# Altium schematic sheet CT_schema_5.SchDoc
size 203 x 169 mm
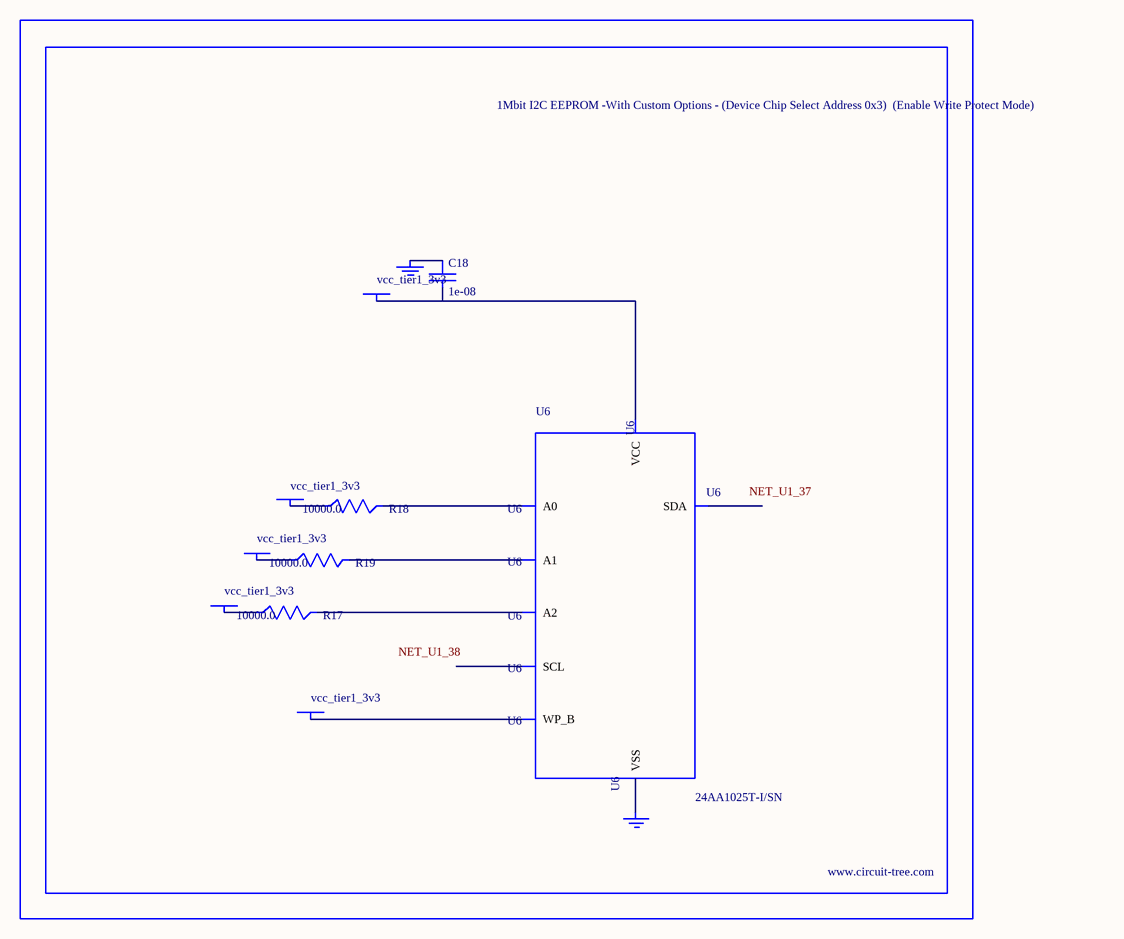
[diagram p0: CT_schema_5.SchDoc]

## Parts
BORDER4  (no value)
C18  1e-08  [C0402]
GND_INSTANCE_4_0  (no value)
GND_INSTANCE_4_1  (no value)
POWER_INSTANCE_4_0  vcc_tier1_3v3
POWER_INSTANCE_4_1  vcc_tier1_3v3
POWER_INSTANCE_4_2  vcc_tier1_3v3
POWER_INSTANCE_4_3  vcc_tier1_3v3
POWER_INSTANCE_4_4  vcc_tier1_3v3
R17  10000.0  [R0603]
R18  10000.0  [R0603]
R19  10000.0  [R0603]
U6  24AA1025T-I/SN  [SOIC-8]

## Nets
NetC18_1: C18.1 GND_INSTANCE_4_0.0(GND)
NetC18_2: C18.2 POWER_INSTANCE_4_4.0(PWR) U6.8(VCC)
NetGND_INSTANCE_4_1_0: GND_INSTANCE_4_1.0(GND) U6.4(VSS)
NetPOWER_INSTANCE_4_0_0: POWER_INSTANCE_4_0.0(PWR) R18.1
NetPOWER_INSTANCE_4_1_0: POWER_INSTANCE_4_1.0(PWR) R19.1
NetPOWER_INSTANCE_4_2_0: POWER_INSTANCE_4_2.0(PWR) R17.1
NetPOWER_INSTANCE_4_3_0: POWER_INSTANCE_4_3.0(PWR) U6.7(WP_B)
NetR17_2: R17.2 U6.3(A2)
NetR18_2: R18.2 U6.1(A0)
NetR19_2: R19.2 U6.2(A1)

Not connected (* = marked no-connect by the designer): U6 5(SDA) 6(SCL)

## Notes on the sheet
- Labels drawn without touching a wire or pin: NET_U1_37, NET_U1_38

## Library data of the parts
BORDER4 = BORDER_PAGE4
C18 = C0402C103K3RAC
GND_INSTANCE_4_0 GND_INSTANCE_4_1 = GND
POWER_INSTANCE_4_0-POWER_INSTANCE_4_4 = PWR
R17-R19 = RC0603JR-0710KL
